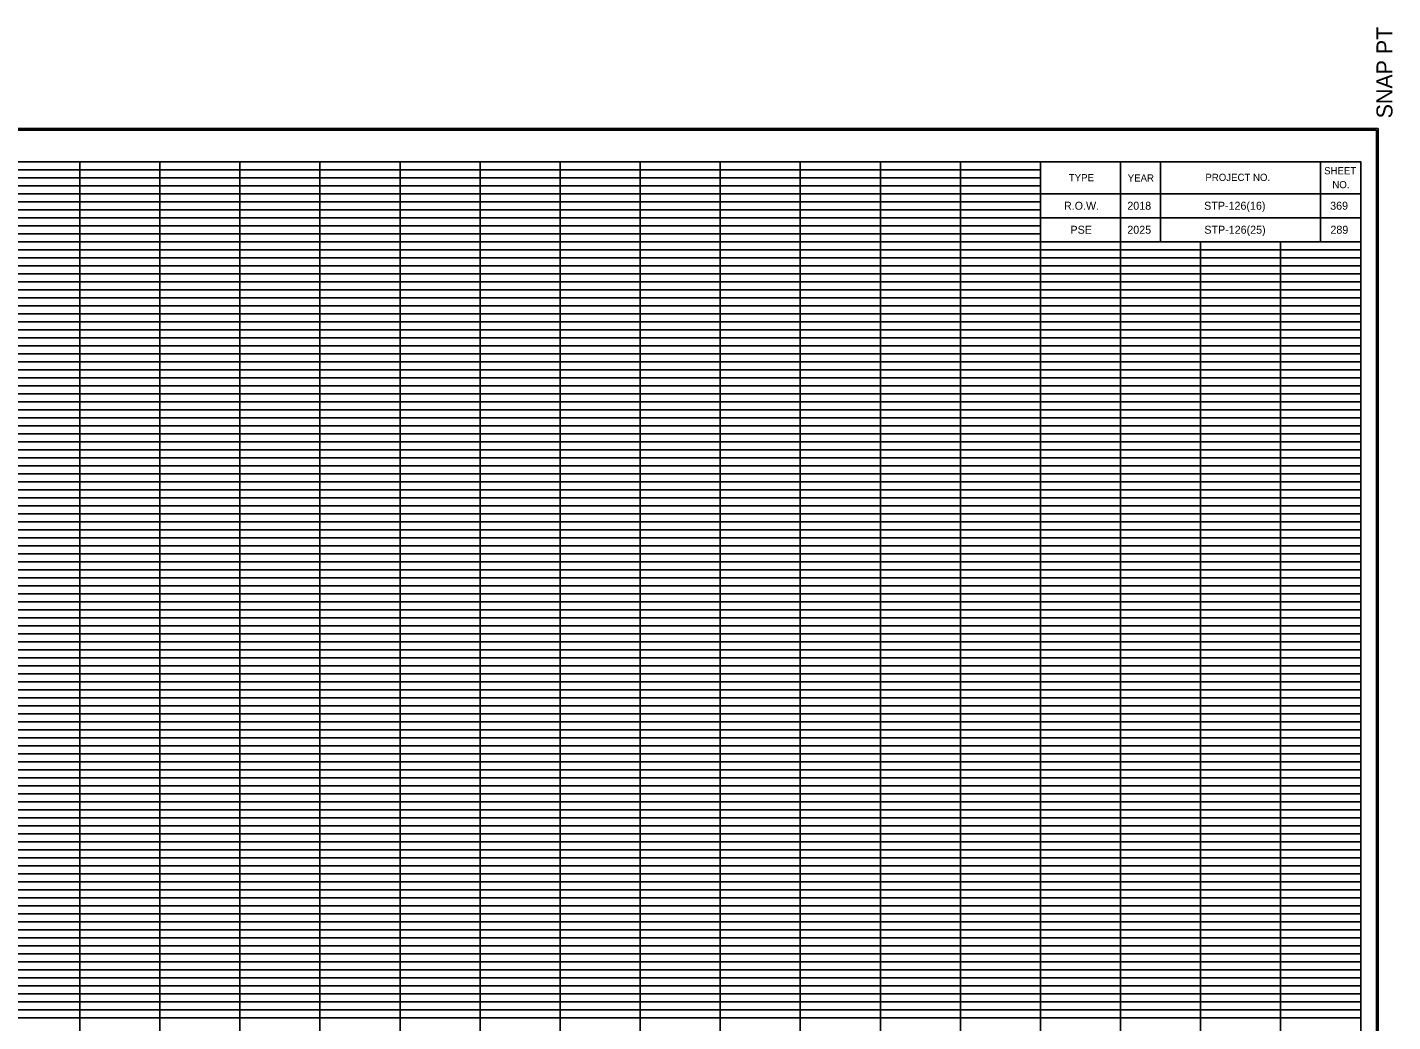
# Model space of a CAD drawing. Extents: x 980 to 1324, y 978 to 1497.
# Drawn here: x 1153.4 to 1324, y 1372.5 to 1496.8 of the extents above; entities that cross this region are included whole.
import ezdxf

# ---------------------------------------------------------------- set-up
doc = ezdxf.new("R2010")
doc.units = 0
for name, color, linetype in [('DESIGN - SCRATCH - User 1', 7, 'Continuous'), ('DESIGN - SHEET - Corner Text', 7, 'Continuous'), ('DESIGN - SHEET - Light Grid', 7, 'Continuous'), ('DESIGN - SHEET - Linework', 7, 'Continuous'), ('DESIGN - SHEET - Plot Shape', 7, 'Continuous')]:
    doc.layers.add(name, color=color, linetype=linetype)

# ---------------------------------------------------------------- blocks, each defined once
blk = doc.blocks.new('XSTSHT')
at = {"layer": 'DESIGN - SCRATCH - User 1'}
for p, q in [((28.5, 20.45), (28.5, 20.45)), ((29.24, 20.45), (29.24, 20.45)), ((30.49, 20.45), (30.49, 20.45)), ((31.74, 20.45), (31.74, 20.45)), ((28.5, 20.15), (28.5, 20.15)), ((29.24, 20.15), (29.24, 20.15)), ((30.49, 20.15), (30.49, 20.15)), ((31.74, 20.15), (31.74, 20.15))]:
    blk.add_line(p, q, dxfattribs=at)
at = {"layer": 'DESIGN - SHEET - Light Grid'}
for p, q in [((8, 20.9), (16, 20.9)), ((16, 20.9), (24, 20.9)), ((24, 20.9), (28, 20.9)), ((8, 20.8), (16, 20.8)), ((8, 20.7), (16, 20.7)), ((16, 20.8), (24, 20.8)), ((16, 20.7), (24, 20.7)), ((24, 20.8), (28, 20.8)), ((24, 20.7), (28, 20.7)), ((8, 20.6), (16, 20.6)), ((8, 20.5), (16, 20.5)), ((16, 20.6), (24, 20.6)), ((16, 20.5), (24, 20.5)), ((24, 20.6), (28, 20.6)), ((24, 20.5), (28, 20.5)), ((8, 20.4), (16, 20.4)), ((8, 20.3), (16, 20.3)), ((16, 20.4), (24, 20.4)), ((16, 20.3), (24, 20.3)), ((24, 20.4), (28, 20.4)), ((24, 20.3), (28, 20.3)), ((8, 20.2), (16, 20.2)), ((16, 20.2), (24, 20.2)), ((24, 20.2), (28, 20.2)), ((8, 20.1), (16, 20.1)), ((16, 20.1), (24, 20.1)), ((24, 20.1), (28, 20.1)), ((8, 19.9), (16, 19.9)), ((8, 19.8), (16, 19.8)), ((16, 19.9), (24, 19.9)), ((16, 19.8), (24, 19.8)), ((24, 19.9), (32, 19.9)), ((24, 19.8), (32, 19.8)), ((8, 19.7), (16, 19.7)), ((16, 19.7), (24, 19.7)), ((24, 19.7), (32, 19.7)), ((8, 19.6), (16, 19.6)), ((8, 19.5), (16, 19.5)), ((16, 19.6), (24, 19.6)), ((16, 19.5), (24, 19.5)), ((24, 19.6), (32, 19.6)), ((24, 19.5), (32, 19.5)), ((8, 19.4), (16, 19.4)), ((8, 19.3), (16, 19.3)), ((16, 19.4), (24, 19.4)), ((16, 19.3), (24, 19.3)), ((24, 19.4), (32, 19.4)), ((24, 19.3), (32, 19.3)), ((8, 19.2), (16, 19.2)), ((16, 19.2), (24, 19.2)), ((24, 19.2), (32, 19.2)), ((8, 19.1), (16, 19.1)), ((16, 19.1), (24, 19.1)), ((24, 19.1), (32, 19.1)), ((8, 18.9), (16, 18.9)), ((8, 18.8), (16, 18.8)), ((16, 18.9), (24, 18.9)), ((16, 18.8), (24, 18.8)), ((24, 18.9), (32, 18.9)), ((24, 18.8), (32, 18.8)), ((8, 18.7), (16, 18.7)), ((8, 18.6), (16, 18.6)), ((16, 18.7), (24, 18.7)), ((16, 18.6), (24, 18.6)), ((24, 18.7), (32, 18.7)), ((24, 18.6), (32, 18.6)), ((8, 18.5), (16, 18.5)), ((16, 18.5), (24, 18.5)), ((24, 18.5), (32, 18.5)), ((8, 18.4), (16, 18.4)), ((8, 18.3), (16, 18.3)), ((16, 18.4), (24, 18.4)), ((16, 18.3), (24, 18.3)), ((24, 18.4), (32, 18.4)), ((24, 18.3), (32, 18.3)), ((8, 18.2), (16, 18.2)), ((8, 18.1), (16, 18.1)), ((16, 18.2), (24, 18.2)), ((16, 18.1), (24, 18.1)), ((24, 18.2), (32, 18.2)), ((24, 18.1), (32, 18.1)), ((8, 17.9), (16, 17.9)), ((8, 17.8), (16, 17.8)), ((16, 17.9), (24, 17.9)), ((16, 17.8), (24, 17.8)), ((24, 17.9), (32, 17.9)), ((24, 17.8), (32, 17.8)), ((8, 17.7), (16, 17.7)), ((8, 17.6), (16, 17.6)), ((16, 17.7), (24, 17.7)), ((16, 17.6), (24, 17.6)), ((24, 17.7), (32, 17.7)), ((24, 17.6), (32, 17.6)), ((8, 17.5), (16, 17.5)), ((8, 17.4), (16, 17.4)), ((16, 17.5), (24, 17.5)), ((16, 17.4), (24, 17.4)), ((24, 17.5), (32, 17.5)), ((24, 17.4), (32, 17.4)), ((8, 17.3), (16, 17.3)), ((16, 17.3), (24, 17.3)), ((24, 17.3), (32, 17.3)), ((8, 17.2), (16, 17.2)), ((8, 17.1), (16, 17.1)), ((16, 17.2), (24, 17.2)), ((16, 17.1), (24, 17.1)), ((24, 17.2), (32, 17.2)), ((24, 17.1), (32, 17.1)), ((8, 16.9), (16, 16.9)), ((16, 16.9), (24, 16.9)), ((24, 16.9), (32, 16.9)), ((8, 16.8), (16, 16.8)), ((16, 16.8), (24, 16.8)), ((24, 16.8), (32, 16.8)), ((8, 16.7), (16, 16.7)), ((8, 16.6), (16, 16.6)), ((16, 16.7), (24, 16.7)), ((16, 16.6), (24, 16.6)), ((24, 16.7), (32, 16.7)), ((24, 16.6), (32, 16.6)), ((8, 16.5), (16, 16.5)), ((8, 16.4), (16, 16.4)), ((16, 16.5), (24, 16.5)), ((16, 16.4), (24, 16.4)), ((24, 16.5), (32, 16.5)), ((24, 16.4), (32, 16.4)), ((8, 16.3), (16, 16.3)), ((16, 16.3), (24, 16.3)), ((24, 16.3), (32, 16.3)), ((8, 16.2), (16, 16.2)), ((8, 16.1), (16, 16.1)), ((16, 16.2), (24, 16.2)), ((16, 16.1), (24, 16.1)), ((24, 16.2), (32, 16.2)), ((24, 16.1), (32, 16.1)), ((8, 15.9), (16, 15.9)), ((16, 15.9), (24, 15.9)), ((24, 15.9), (32, 15.9)), ((8, 15.8), (16, 15.8)), ((8, 15.7), (16, 15.7)), ((16, 15.8), (24, 15.8)), ((16, 15.7), (24, 15.7)), ((24, 15.8), (32, 15.8)), ((24, 15.7), (32, 15.7)), ((8, 15.6), (16, 15.6)), ((16, 15.6), (24, 15.6)), ((24, 15.6), (32, 15.6)), ((8, 15.5), (16, 15.5)), ((8, 15.4), (16, 15.4)), ((16, 15.5), (24, 15.5)), ((16, 15.4), (24, 15.4)), ((24, 15.5), (32, 15.5)), ((24, 15.4), (32, 15.4)), ((8, 15.3), (16, 15.3)), ((8, 15.2), (16, 15.2)), ((16, 15.3), (24, 15.3)), ((16, 15.2), (24, 15.2)), ((24, 15.3), (32, 15.3)), ((24, 15.2), (32, 15.2)), ((8, 15.1), (16, 15.1)), ((16, 15.1), (24, 15.1)), ((24, 15.1), (32, 15.1)), ((8, 14.9), (16, 14.9)), ((16, 14.9), (24, 14.9)), ((24, 14.9), (32, 14.9)), ((8, 14.8), (16, 14.8)), ((8, 14.7), (16, 14.7)), ((16, 14.8), (24, 14.8)), ((16, 14.7), (24, 14.7)), ((24, 14.8), (32, 14.8)), ((24, 14.7), (32, 14.7)), ((8, 14.6), (16, 14.6)), ((8, 14.5), (16, 14.5)), ((16, 14.6), (24, 14.6)), ((16, 14.5), (24, 14.5)), ((24, 14.6), (32, 14.6)), ((24, 14.5), (32, 14.5)), ((8, 14.4), (16, 14.4)), ((16, 14.4), (24, 14.4)), ((24, 14.4), (32, 14.4)), ((8, 14.3), (16, 14.3)), ((8, 14.2), (16, 14.2)), ((16, 14.3), (24, 14.3)), ((16, 14.2), (24, 14.2)), ((24, 14.3), (32, 14.3)), ((24, 14.2), (32, 14.2)), ((8, 14.1), (16, 14.1)), ((16, 14.1), (24, 14.1)), ((24, 14.1), (32, 14.1)), ((8, 13.9), (16, 13.9)), ((16, 13.9), (24, 13.9)), ((24, 13.9), (32, 13.9)), ((8, 13.8), (16, 13.8)), ((8, 13.7), (16, 13.7)), ((16, 13.8), (24, 13.8)), ((16, 13.7), (24, 13.7)), ((24, 13.8), (32, 13.8)), ((24, 13.7), (32, 13.7)), ((8, 13.6), (16, 13.6)), ((8, 13.5), (16, 13.5)), ((16, 13.6), (24, 13.6)), ((16, 13.5), (24, 13.5)), ((24, 13.6), (32, 13.6)), ((24, 13.5), (32, 13.5)), ((8, 13.4), (16, 13.4)), ((16, 13.4), (24, 13.4)), ((24, 13.4), (32, 13.4)), ((8, 13.3), (16, 13.3)), ((8, 13.2), (16, 13.2)), ((16, 13.3), (24, 13.3)), ((16, 13.2), (24, 13.2)), ((24, 13.3), (32, 13.3)), ((24, 13.2), (32, 13.2)), ((8, 13.1), (16, 13.1)), ((16, 13.1), (24, 13.1)), ((24, 13.1), (32, 13.1)), ((8, 12.9), (16, 12.9)), ((8, 12.8), (16, 12.8)), ((16, 12.9), (24, 12.9)), ((16, 12.8), (24, 12.8)), ((24, 12.9), (32, 12.9)), ((24, 12.8), (32, 12.8)), ((8, 12.7), (16, 12.7)), ((16, 12.7), (24, 12.7)), ((24, 12.7), (32, 12.7)), ((8, 12.6), (16, 12.6)), ((8, 12.5), (16, 12.5)), ((16, 12.6), (24, 12.6)), ((16, 12.5), (24, 12.5)), ((24, 12.6), (32, 12.6)), ((24, 12.5), (32, 12.5)), ((8, 12.4), (16, 12.4)), ((8, 12.3), (16, 12.3)), ((16, 12.4), (24, 12.4)), ((16, 12.3), (24, 12.3)), ((24, 12.4), (32, 12.4)), ((24, 12.3), (32, 12.3)), ((8, 12.2), (16, 12.2)), ((16, 12.2), (24, 12.2)), ((24, 12.2), (32, 12.2)), ((8, 12.1), (16, 12.1)), ((16, 12.1), (24, 12.1)), ((24, 12.1), (32, 12.1)), ((8, 11.9), (16, 11.9)), ((8, 11.8), (16, 11.8)), ((16, 11.9), (24, 11.9)), ((16, 11.8), (24, 11.8)), ((24, 11.9), (32, 11.9)), ((24, 11.8), (32, 11.8)), ((8, 11.7), (16, 11.7)), ((8, 11.6), (16, 11.6)), ((16, 11.7), (24, 11.7)), ((16, 11.6), (24, 11.6)), ((24, 11.7), (32, 11.7)), ((24, 11.6), (32, 11.6)), ((8, 11.5), (16, 11.5)), ((16, 11.5), (24, 11.5)), ((24, 11.5), (32, 11.5)), ((8, 11.4), (16, 11.4)), ((8, 11.3), (16, 11.3)), ((16, 11.4), (24, 11.4)), ((16, 11.3), (24, 11.3)), ((24, 11.4), (32, 11.4)), ((24, 11.3), (32, 11.3)), ((8, 11.2), (16, 11.2)), ((8, 11.1), (16, 11.1)), ((16, 11.2), (24, 11.2)), ((16, 11.1), (24, 11.1)), ((24, 11.2), (32, 11.2)), ((24, 11.1), (32, 11.1)), ((8, 10.9), (16, 10.9)), ((8, 10.8), (16, 10.8)), ((16, 10.9), (24, 10.9)), ((16, 10.8), (24, 10.8)), ((24, 10.9), (32, 10.9)), ((24, 10.8), (32, 10.8)), ((8, 10.7), (16, 10.7)), ((8, 10.6), (16, 10.6)), ((16, 10.7), (24, 10.7)), ((16, 10.6), (24, 10.6)), ((24, 10.7), (32, 10.7)), ((24, 10.6), (32, 10.6)), ((8, 10.5), (16, 10.5)), ((16, 10.5), (24, 10.5)), ((24, 10.5), (32, 10.5)), ((8, 10.4), (16, 10.4)), ((8, 10.3), (16, 10.3)), ((16, 10.4), (24, 10.4)), ((16, 10.3), (24, 10.3)), ((24, 10.4), (32, 10.4)), ((24, 10.3), (32, 10.3))]:
    blk.add_line(p, q, dxfattribs=at)
at = {"layer": 'DESIGN - SHEET - Linework'}
for p, q in [((-1.823, 21.414), (32.217, 21.414)), ((32.217, 21.414), (32.217, -0.414)), ((16, 0), (16, 21)), ((17, 0), (17, 21)), ((18, 0), (18, 21)), ((19, 0), (19, 21)), ((20, 0), (20, 21)), ((21, 0), (21, 21)), ((22, 0), (22, 21)), ((23, 0), (23, 21)), ((24, 0), (24, 21)), ((25, 0), (25, 21)), ((26, 0), (26, 21)), ((27, 0), (27, 21)), ((0, 20), (28, 20)), ((28, 0), (28, 20)), ((29, 0), (29, 20)), ((30, 0), (30, 20)), ((31, 0), (31, 20)), ((0, 19), (32, 19)), ((0, 18), (32, 18)), ((0, 17), (32, 17)), ((0, 16), (32, 16)), ((0, 15), (32, 15)), ((0, 14), (32, 14)), ((0, 13), (32, 13)), ((0, 12), (32, 12)), ((0, 11), (32, 11))]:
    blk.add_line(p, q, dxfattribs=at)
for points in [[(0, 21), (0, 0), (32, 0), (32, 21), (0, 21)], [(28, 21), (28, 20), (32, 20), (32, 21), (31.5, 21), (31.5, 20), (29.5, 20), (29.5, 21), (29, 21), (29, 20), (32, 20), (28, 20), (28, 20.3), (32, 20.3), (32, 20.6), (28, 20.6)]]:
    blk.add_lwpolyline(points, dxfattribs=at)
at = {"layer": 'DESIGN - SHEET - Plot Shape'}
for points in [[(-1.803, 21.394), (32.197, 21.394), (32.197, -0.394), (-1.803, -0.394)], [(-0.85, 21), (32, 21), (32, -0.25), (-0.85, -0.25)]]:
    blk.add_lwpolyline(points, close=True, dxfattribs=at)
at = {"layer": 'DESIGN - SHEET - Corner Text'}
blk.add_text('  SNAP PT', height=0.2, rotation=90, dxfattribs=at).set_placement((32.397, 21.394))
for s, p in [('TYPE', (28.354, 20.756)), ('YEAR', (29.09, 20.752)), ('PROJECT NO.', (30.06, 20.76)), ('SHEET', (31.543, 20.843)), ('NO.', (31.646, 20.669))]:
    blk.add_text(s, height=0.09, dxfattribs=at).set_placement(p)

msp = doc.modelspace()

# ---------------------------------------------------------------- linework, layer by layer
at = {"layer": 'DESIGN - SHEET - Plot Shape'}
msp.add_lwpolyline([(991.5, 1267.5), (1320, 1267.5), (1320, 1480), (991.5, 1480)], close=True, dxfattribs=at)

# ---------------------------------------------------------------- block references
at = {"layer": 'DESIGN - SHEET - Corner Text', "xscale": 10, "yscale": 10}
msp.add_blockref('XSTSHT', (1000, 1270), dxfattribs=at)

# ---------------------------------------------------------------- texts
at = {"layer": 'DESIGN - SHEET - Corner Text'}
for s, p in [('R.O.W.', (1282.94, 1474)), ('2018', (1290.85, 1474)), ('STP-126(16)', (1300.45, 1474)), ('369', (1316.19, 1474)), ('PSE', (1283.75, 1471)), ('2025', (1290.85, 1471)), ('STP-126(25)', (1300.47, 1471)), ('289', (1316.22, 1471))]:
    msp.add_text(s, height=1, dxfattribs=at).set_placement(p)

doc.saveas('drawing.dxf')
